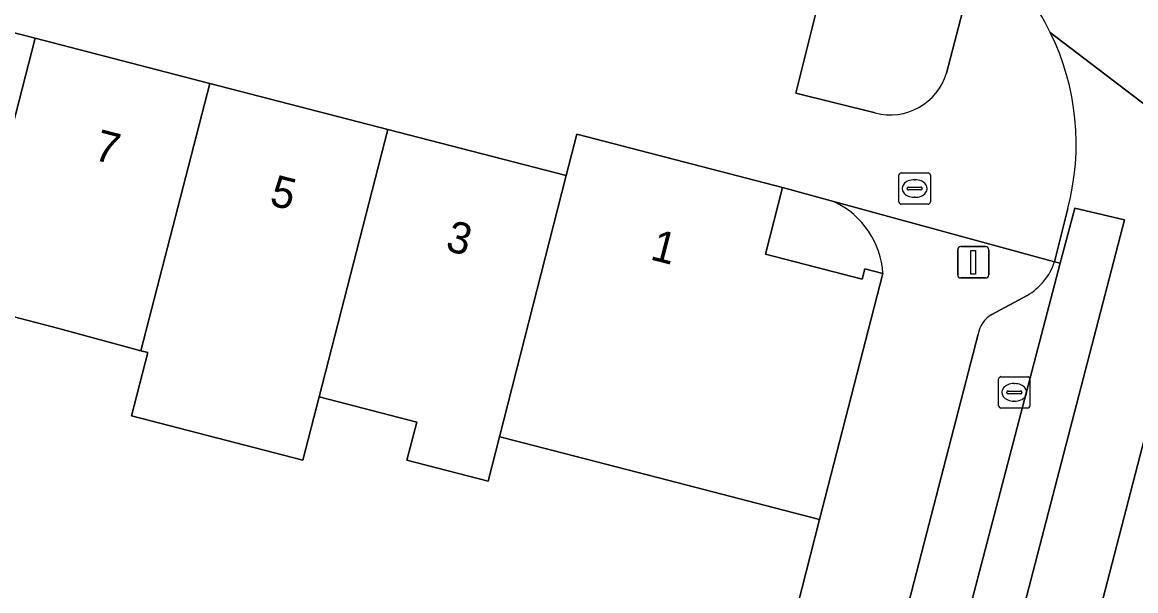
# Model space of a CAD drawing. Extents: x 163683 to 164494, y 382709 to 383872.
# Drawn here: x 164228.8 to 164264.34, y 383158.75 to 383176.88 of the extents above; entities that cross this region are included whole.
import ezdxf

# ---------------------------------------------------------------- set-up
doc = ezdxf.new("R2010")
doc.units = 0
for name, color, linetype in [('IMGEO_Brandkraan', 7, 'Continuous'), ('IMGEO_Erf', 7, 'Continuous'), ('IMGEO_Groenvoorziening', 7, 'Continuous'), ('IMGEO_Kolk', 7, 'Continuous'), ('IMGEO_Lichtmast', 7, 'Continuous'), ('IMGEO_Pand', 7, 'Continuous'), ('IMGEO_Pand_nummerreeks', 7, 'Continuous'), ('IMGEO_Parkeervlak_open', 7, 'Continuous'), ('IMGEO_Rijbaan_lokaal_gesloten', 7, 'Continuous'), ('IMGEO_Rijbaan_lokaal_open', 7, 'Continuous'), ('IMGEO_Voetpad_open', 7, 'Continuous')]:
    doc.layers.add(name, color=color, linetype=linetype)

msp = doc.modelspace()

# ---------------------------------------------------------------- linework, layer by layer
at = {"layer": 'IMGEO_Brandkraan'}
for p, q in [((164256.783, 383171.153), (164256.783, 383172.005)), ((164256.858, 383172.079), (164257.71, 383172.079)), ((164257.271, 383171.859), (164257.296, 383171.859)), ((164257.784, 383172.005), (164257.784, 383171.153)), ((164257.042, 383171.573), (164257.042, 383171.585)), ((164257.48, 383171.536), (164257.082, 383171.536)), ((164257.085, 383171.622), (164257.483, 383171.622)), ((164257.526, 383171.585), (164257.526, 383171.573)), ((164257.71, 383171.079), (164256.858, 383171.079)), ((164257.294, 383171.299), (164257.269, 383171.299))]:
    msp.add_line(p, q, dxfattribs=at)
for points in [[(164256.783, 383171.153), (164256.783, 383172.005)], [(164256.858, 383172.079), (164257.71, 383172.079)], [(164257.784, 383172.005), (164257.784, 383171.153)], [(164257.71, 383171.079), (164256.858, 383171.079)]]:
    msp.add_lwpolyline(points, dxfattribs=at)
for centre, radius, start, end in [((164256.86, 383172.003), 0.0765, 91.552, 178.448), ((164256.86, 383172.003), 0.0765, 91.552, 178.448), ((164257.708, 383172.003), 0.0765, 1.552, 88.448), ((164257.708, 383172.003), 0.0765, 1.552, 88.448), ((164257.082, 383171.582), 0.0403, 85.8775, 175.7526), ((164257.079, 383171.572), 0.0366, 178.938, 274.7102), ((164257.483, 383171.579), 0.043, 264.8664, 352.4533), ((164257.487, 383171.584), 0.0386, 1.7309, 96.639), ((164256.86, 383171.155), 0.0765, 181.552, 268.448), ((164256.86, 383171.155), 0.0765, 181.552, 268.448), ((164257.708, 383171.155), 0.0765, 271.552, 358.448), ((164257.708, 383171.155), 0.0765, 271.552, 358.448)]:
    msp.add_arc(centre, radius, start, end, dxfattribs=at)
for centre, major_axis, ratio, start_param, end_param in [((164257.27, 383171.579), (-0.387, 0.002), 0.722429, 4.712389, 7.853982), ((164257.295, 383171.579), (-0.39, 0.002), 0.717154, 1.570796, 4.712389)]:
    msp.add_ellipse(centre, major_axis=major_axis, ratio=ratio, start_param=start_param, end_param=end_param, dxfattribs=at)
at = {"layer": 'IMGEO_Erf'}
for points in [[(164253.068, 383171.616), (164252.518, 383169.486), (164255.611, 383168.689), (164255.695, 383169.015), (164256.27, 383168.867)], [(164254.734, 383171.15), (164253.068, 383171.616)], [(164249.406, 383162.272), (164244.128, 383163.633), (164244.031, 383163.658), (164243.669, 383162.241), (164241.077, 383162.91), (164241.392, 383164.132), (164238.271, 383164.937), (164237.75, 383162.914), (164232.281, 383164.325), (164232.81, 383166.345), (164232.586, 383166.405), (164229.966, 383167.12), (164227.019, 383167.88)], [(164226.727, 383155.841), (164230.22, 383154.893), (164229.953, 383153.91), (164235.347, 383152.554), (164239.872, 383151.416), (164238.952, 383147.757), (164244.045, 383146.521), (164244.956, 383150.051), (164247.395, 383149.422), (164246.484, 383145.892), (164250.15, 383144.957), (164254.247, 383161.023), (164249.406, 383162.272)]]:
    msp.add_lwpolyline(points, dxfattribs=at)
msp.add_arc((164253.55, 383168.695), 2.725, 3.6129, 64.2524, dxfattribs=at)
at = {"layer": 'IMGEO_Groenvoorziening'}
for points in [[(164256.511, 383180.717), (164254.604, 383181.213), (164254.494, 383180.764), (164253.171, 383181.112), (164254.163, 383177.301), (164253.496, 383174.624), (164256.02, 383173.992)], [(164258.301, 383175.263), (164259.2, 383178.737), (164258.684, 383179.159), (164257.851, 383179.706), (164256.914, 383180.082), (164256.381, 383180.255), (164256.511, 383180.717)]]:
    msp.add_lwpolyline(points, dxfattribs=at)
msp.add_arc((164256.5, 383175.813), 1.883, 255.2239, 343.0303, dxfattribs=at)
at = {"layer": 'IMGEO_Kolk'}
for p, q in [((164259.964, 383164.652), (164259.964, 383165.504)), ((164260.039, 383165.578), (164260.891, 383165.578)), ((164260.452, 383165.358), (164260.477, 383165.358)), ((164260.965, 383165.504), (164260.965, 383164.652)), ((164260.223, 383165.072), (164260.223, 383165.084)), ((164260.661, 383165.035), (164260.263, 383165.035)), ((164260.266, 383165.121), (164260.664, 383165.121)), ((164260.707, 383165.084), (164260.707, 383165.072)), ((164260.475, 383164.798), (164260.45, 383164.798)), ((164260.891, 383164.578), (164260.039, 383164.578))]:
    msp.add_line(p, q, dxfattribs=at)
for points in [[(164259.964, 383164.652), (164259.964, 383165.504)], [(164260.039, 383165.578), (164260.891, 383165.578)], [(164260.965, 383165.504), (164260.965, 383164.652)], [(164260.891, 383164.578), (164260.039, 383164.578)]]:
    msp.add_lwpolyline(points, dxfattribs=at)
for centre, radius, start, end in [((164260.041, 383165.502), 0.0765, 91.552, 178.448), ((164260.041, 383165.502), 0.0765, 91.552, 178.448), ((164260.889, 383165.502), 0.0765, 1.552, 88.448), ((164260.889, 383165.502), 0.0765, 1.552, 88.448), ((164260.263, 383165.081), 0.0403, 85.8775, 175.7526), ((164260.26, 383165.071), 0.0366, 178.938, 274.7102), ((164260.664, 383165.078), 0.043, 264.8664, 352.4533), ((164260.668, 383165.083), 0.0386, 1.7309, 96.639), ((164260.041, 383164.654), 0.0765, 181.552, 268.448), ((164260.041, 383164.654), 0.0765, 181.552, 268.448), ((164260.889, 383164.654), 0.0765, 271.552, 358.448), ((164260.889, 383164.654), 0.0765, 271.552, 358.448)]:
    msp.add_arc(centre, radius, start, end, dxfattribs=at)
for centre, major_axis, ratio, start_param, end_param in [((164260.451, 383165.078), (-0.387, 0.002), 0.722429, 4.712389, 7.853982), ((164260.476, 383165.078), (-0.39, 0.002), 0.717154, 1.570796, 4.712389)]:
    msp.add_ellipse(centre, major_axis=major_axis, ratio=ratio, start_param=start_param, end_param=end_param, dxfattribs=at)
at = {"layer": 'IMGEO_Lichtmast'}
for p, q in [((164258.659, 383168.827), (164258.659, 383169.627)), ((164258.659, 383169.627), (164258.659, 383168.827)), ((164258.759, 383169.727), (164259.549, 383169.727)), ((164259.549, 383169.727), (164258.759, 383169.727)), ((164259.649, 383169.627), (164259.649, 383168.827)), ((164259.649, 383168.827), (164259.649, 383169.627)), ((164259.549, 383168.727), (164258.759, 383168.727)), ((164258.759, 383168.727), (164259.549, 383168.727))]:
    msp.add_line(p, q, dxfattribs=at)
msp.add_lwpolyline([(164259.079, 383169.602), (164259.229, 383169.602), (164259.229, 383168.852), (164259.079, 383168.852), (164259.079, 383169.602)], dxfattribs=at)
for centre, start, end in [((164258.759, 383169.627), 90, 180), ((164258.759, 383169.627), 90, 180), ((164259.549, 383169.627), 0, 90), ((164259.549, 383169.627), 360, 90), ((164258.759, 383168.827), 180, 270), ((164258.759, 383168.827), 180, 270), ((164259.549, 383168.827), 270, 0), ((164259.549, 383168.827), 270, 0)]:
    msp.add_arc(centre, 0.1, start, end, dxfattribs=at)
at = {"layer": 'IMGEO_Pand'}
for points in [[(164229.208, 383176.371), (164223.493, 383177.845), (164221.646, 383170.68), (164221.304, 383169.354), (164224.387, 383168.559), (164227.019, 383167.88)], [(164234.784, 383174.933), (164229.208, 383176.371), (164227.019, 383167.88), (164229.966, 383167.12), (164232.586, 383166.405)], [(164240.47, 383173.467), (164234.784, 383174.933), (164232.586, 383166.405), (164232.81, 383166.345), (164232.281, 383164.325), (164237.75, 383162.914), (164238.271, 383164.937)], [(164246.163, 383171.999), (164240.47, 383173.467), (164238.271, 383164.937), (164241.392, 383164.132), (164241.077, 383162.91), (164243.669, 383162.241), (164244.031, 383163.658)], [(164256.27, 383168.867), (164255.695, 383169.015), (164255.611, 383168.689), (164252.518, 383169.486), (164253.068, 383171.616), (164246.501, 383173.309), (164246.163, 383171.999), (164244.031, 383163.658), (164244.128, 383163.633), (164249.406, 383162.272), (164254.247, 383161.023)]]:
    msp.add_lwpolyline(points, close=True, dxfattribs=at)
at = {"layer": 'IMGEO_Parkeervlak_open'}
for points in [[(164261.932, 383169.194), (164261.75, 383169.242)], [(164249.477, 383121.644), (164261.932, 383169.194)], [(164260.873, 383168.172), (164259.743, 383167.557)], [(164259.315, 383166.935), (164254.431, 383148.07)]]:
    msp.add_lwpolyline(points, dxfattribs=at)
for centre, radius, start, end in [((164259.91, 383169.856), 1.94, 299.7699, 341.5522), ((164260.163, 383166.81), 0.857, 119.3235, 171.6126)]:
    msp.add_arc(centre, radius, start, end, dxfattribs=at)
at = {"layer": 'IMGEO_Rijbaan_lokaal_gesloten'}
for points in [[(164252.171, 383115.634), (164255.758, 383122.164), (164264.899, 383157.351), (164266.776, 383164.735), (164268.655, 383172.017), (164266.924, 383172.51)], [(164247.459, 383107.056), (164263.984, 383170.576), (164262.392, 383170.95), (164261.932, 383169.194), (164249.477, 383121.644), (164240.427, 383087.096), (164241.649, 383086.771), (164247.274, 383106.72)]]:
    msp.add_lwpolyline(points, close=True, dxfattribs=at)
at = {"layer": 'IMGEO_Rijbaan_lokaal_open'}
for points in [[(164252.171, 383115.634), (164266.924, 383172.51), (164261.612, 383176.558)], [(164261.612, 383176.558), (164266.924, 383172.51), (164268.655, 383172.017), (164268.973, 383173.248)], [(164262.169, 383170.941), (164261.75, 383169.242), (164261.932, 383169.194), (164262.392, 383170.95), (164263.984, 383170.576), (164247.459, 383107.056), (164252.171, 383115.634)]]:
    msp.add_lwpolyline(points, dxfattribs=at)
for centre, radius, start, end in [((164254.406, 383173.01), 8.032, 26.2152, 69.4912), ((164254.405, 383173.007), 8.035, 345.0984, 26.2278)]:
    msp.add_arc(centre, radius, start, end, dxfattribs=at)
at = {"layer": 'IMGEO_Voetpad_open'}
for points in [[(164205.266, 383183.917), (164206.288, 383183.703), (164212.82, 383182.019), (164212.476, 383180.686), (164218.119, 383179.231), (164223.493, 383177.845), (164229.208, 383176.371), (164234.784, 383174.933), (164240.47, 383173.467), (164246.163, 383171.999), (164246.501, 383173.309), (164253.068, 383171.616), (164254.734, 383171.15), (164261.75, 383169.242), (164262.169, 383170.941)], [(164256.02, 383173.992), (164253.496, 383174.624), (164254.163, 383177.301), (164253.171, 383181.112), (164254.494, 383180.764), (164254.604, 383181.213), (164253.352, 383181.538), (164253.238, 383181.56)], [(164257.22, 383180.533), (164256.511, 383180.717), (164256.381, 383180.255), (164256.914, 383180.082), (164257.851, 383179.706), (164258.684, 383179.159), (164259.2, 383178.737), (164258.301, 383175.263)], [(164261.75, 383169.242), (164254.734, 383171.15)], [(164256.27, 383168.867), (164254.247, 383161.023), (164250.15, 383144.957), (164249.772, 383143.475), (164235.416, 383087.174)], [(164259.743, 383167.557), (164260.873, 383168.172)], [(164251.868, 383138.243), (164250.825, 383138.552), (164253.343, 383148.348), (164254.431, 383148.07), (164259.315, 383166.935)]]:
    msp.add_lwpolyline(points, dxfattribs=at)
for centre, radius, start, end in [((164254.406, 383173.01), 8.032, 26.2152, 69.4912), ((164254.405, 383173.007), 8.035, 345.0984, 26.2278), ((164256.5, 383175.813), 1.883, 255.2239, 343.0303), ((164253.55, 383168.695), 2.725, 3.6129, 64.2524), ((164259.91, 383169.856), 1.94, 299.7699, 341.5522), ((164260.163, 383166.81), 0.857, 119.3235, 171.6126)]:
    msp.add_arc(centre, radius, start, end, dxfattribs=at)

# ---------------------------------------------------------------- texts
at = {"layer": 'IMGEO_Pand_nummerreeks'}
for s, rotation, p in [('7', 345.5385, (164231.042, 383172.511)), ('5', 345.5385, (164236.657, 383171.063)), ('3', 345.5385, (164242.272, 383169.615)), ('1', 345.5443, (164248.81, 383169.327))]:
    msp.add_text(s, height=1, rotation=rotation, dxfattribs=at).set_placement(p)

doc.saveas('drawing.dxf')
